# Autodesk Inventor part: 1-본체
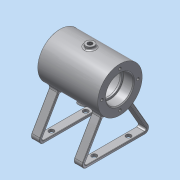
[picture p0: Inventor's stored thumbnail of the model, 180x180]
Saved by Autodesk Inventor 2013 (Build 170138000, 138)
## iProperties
Created: 2016-03
Part Number: 1-본체
Material: 알루미늄 6061
Document SubType Name: Modeling
Designer: Administrator
Mass: 213.146 g
Surface Area: 333.946 cm^2
Volume: 78.6517 cm^3
Density: 2.71 g/cm^3
Author: Administrator
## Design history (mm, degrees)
sketch "스케치1"
  geometry: C1 r 26 at (0, 0); 1 further point
  constraints: 1 centre point, 1 coincident
  dimensions: "d0" = 52 diameter of C1
extrude "돌출1" new body sketch "스케치1" stored distance "d2" = 70; taper "d3" = 0 deg
node "작업 평면1"
sketch "스케치2"
  geometry: C1 r 5 at (0, 0); 1 further point
  constraints: 1 centre point, 1 coincident
  dimensions: "d5" = 10 diameter of C1
extrude "돌출2" join sketch "스케치2" distance "d7" = 26; taper "d8" = 0 deg
sketch "스케치3"
  geometry: L1 (0, 0)-(0, -26); L2 (0, 0)-(7.506, -28.012); L3 (-1.968, -15.836)-(1.71, -29.565); L4 (1.71, -29.565)-(7.506, -28.012); L5 (7.506, -28.012)-(3.827, -14.283); L6 (3.827, -14.283)-(-1.968, -15.836); 1 further point
  constraints: 12 end point, 3 parallel, 1 collinear, 1 perpendicular, 1 vertical, 1 vertical alignment, 1 other
  dimensions: "d9" = 15 deg angle of L2 L1; "d10" = 12 diameter of L3 L2; "d12" = 29 distance from line of L4 point (0, 0)
revolve "회전1" sketch "스케치3" stored, may be unused: angle "d13" = 90 deg
node "작업 평면2"
sketch "스케치4"
  geometry: L1 (-16.613, -20)-(-38.264, -57.5); L2 (-33.934, -65)-(33.934, -65); L3 (38.264, -57.5)-(16.613, -20); L4 (0, 0)-(0, -65); L5 (-16.613, -20)-(16.613, -20); A1 r 5 centre (-33.934, -60) between (-38.264, -57.5) and (-33.934, -65); A2 r 5 centre (33.934, -60) between (33.934, -65) and (38.264, -57.5); A3 r 26 centre (0, 0) between (-16.613, -20) and (16.613, -20) reference
  constraints: 10 end point, 7 point on circle, 3 tangent, 2 centre point, 1 equal length, 1 equal radius, 1 horizontal, 1 midpoint, 1 perpendicular, 1 vertical alignment
  dimensions: "d16" = 5 radius of A1; "d20" = 45 distance between parallel lines of L2 L5; "d21" = 65 distance from line of L4.start L2; "d23" = 30 deg angle of L4 L1; "d24" = 30 deg angle of L3 L4
extrude "돌출3" new body sketch "스케치4" distance "d25" = 10; taper "d26" = 0 deg
sketch "스케치5"
  geometry: L1 (-16.613, -20)-(-38.264, -57.5) reference; L2 (38.264, -57.5)-(16.613, -20) reference; L3 (-33.934, -65)-(33.934, -65) reference; L4 (-14.183, -21.791)-(-35.666, -59); L5 (-33.934, -62)-(33.934, -62); L6 (35.666, -59)-(14.183, -21.791); A1 r 5 centre (-33.934, -60) between (-38.264, -57.5) and (-33.934, -65) reference; A2 r 26 centre (0, 0) between (-16.613, -20) and (16.613, -20) reference; A3 r 5 centre (33.934, -60) between (33.934, -65) and (38.264, -57.5) reference; A4 r 2 centre (-33.934, -60) between (-35.666, -59) and (-33.934, -62); A5 r 2 centre (33.934, -60) between (33.934, -62) and (35.666, -59); A6 r 26 centre (0, 0) between (-14.183, -21.791) and (14.183, -21.791); 1 further point
  constraints: 8 end point, 8 point on circle, 3 centre point, 1 coincident, 1 concentric, 2 other
  dimensions: "d27" = 3 distance between parallel lines of L1 L4; "d28" = 3 distance between parallel lines of L2 L6; "d29" = 3 distance between parallel lines of L3 L5
  node "투영된 루프2"
feature "결합1"
  node "솔리드2"
extrude "돌출4" cut sketch "스케치5" distance "d30" = 10; taper "d31" = 0 deg
node "작업 평면4"
sketch "스케치7"
  geometry: L1 (-6.533, -4.268)-(-6.533, 4.268); L2 (-6.533, 4.268)-(6.533, 4.268); L3 (6.533, 4.268)-(6.533, -4.268); L4 (6.533, -4.268)-(-6.533, -4.268); L5 (-26, -35)-(26, -35) reference; L6 (-26, -35)-(-26, 35) reference; 4 further points
  constraints: 2 midpoint, 1 horizontal alignment, 1 vertical alignment, 2 other
  dimensions: "d38" = 26 distance from line of L6 point (0, 0); "d39" = 35 distance from line of point (0, 0) L5; "d40" = 13.0662 distance between parallel lines of L1 L3; "d41" = 8.53659 distance between parallel lines of L2 L4; "d42" = 6.5331 distance from line of point (0, 0) L3
feature "엠보싱2" sketch "스케치7" dims "d16" = 5, "d20" = 45, "d21" = 65, "d23" = 30 deg, "d24" = 30 deg, "d43" = 0.5, "d44" = 0
hole "구멍1" diameter "d47" = 28; stored, may be unused: countersink angle "d51" = 90 deg, drill point angle "d53" = 0 deg; dims "d45" = 10, "d46" = 10, "d48" = 6, "d49" = 32, "d50" = 12, "d52" = 8
hole "구멍2" diameter "d56" = 32; stored, may be unused: countersink angle "d60" = 90 deg, drill point angle "d62" = 0 deg; dims "d54" = 10, "d55" = 10, "d57" = 6, "d58" = 32, "d59" = 12, "d61" = 12
sketch "스케치8"
  geometry: L1 (-16, 35)-(16, 35) reference; L2 (16, -35)-(-16, -35) reference; L3 (0, 35)-(0, -35); L4 (18, 21)-(0, 21); L5 (0, 21)-(0, -21); L6 (0, -21)-(18, -21); L7 (21, -18)-(21, 18); A1 r 3 centre (18, 18) between (21, 18) and (18, 21); A2 r 3 centre (18, -18) between (18, -21) and (21, -18); 4 further points
  constraints: 10 end point, 4 midpoint, 4 point on circle, 4 tangent, 2 centre point, 2 coincident, 2 parallel, 1 equal radius, 1 horizontal, 1 perpendicular, 1 vertical alignment
  dimensions: "d68" = 42 diameter of L7 L3; "d70" = 42 distance between parallel lines of L4 L6; "d71" = 3 radius of A1
revolve "회전2" sketch "스케치8" stored, may be unused: angle "d72" = 90 deg
sketch "스케치9"
  geometry: 2 further points
  constraints: 1 vertical alignment
  dimensions: "d73" = 21 distance of point (0, 0) point (0, 21)
hole "구멍3" sketch "스케치9" at (0, 21) diameter "d74" = 3.242; stored, may be unused: countersink angle "d78" = 90 deg, drill point angle "d80" = 118 deg; dims "d75" = 8, "d76" = 32, "d77" = 12, "d79" = 10
sketch "스케치10"
  geometry: L1 (-5, 0)-(-5, -10) reference; L2 (-5, -50)-(-5, -60) reference; 7 further points
  constraints: 4 horizontal alignment, 2 midpoint, 2 vertical alignment
  dimensions: "d84" = 20 horizontal distance of point (33.934, -30) point (13.934, -5); "d85" = 40 distance of point (53.934, -5) point (13.934, -5)
hole "구멍4" sketch "스케치10" at (13.934, -5), (53.934, -5), (13.934, -55), (53.934, -55) diameter "d86" = 6; stored, may be unused: countersink angle "d90" = 90 deg, drill point angle "d92" = 118 deg; dims "d87" = 6, "d88" = 32, "d89" = 12, "d91" = 10
hole "구멍5" diameter "d95" = 5.188; stored, may be unused: countersink angle "d99" = 90 deg, drill point angle "d101" = 0 deg; dims "d96" = 19, "d97" = 32, "d98" = 12, "d100" = 20, "d104" = 10, "d105" = 10
hole "구멍6" diameter "d106" = 5.188; stored, may be unused: countersink angle "d110" = 90 deg, drill point angle "d112" = 0 deg; dims "d102" = 10, "d103" = 10, "d107" = 14, "d108" = 32, "d109" = 12, "d111" = 15
fillet "모깎기1" dims "d113" = 2
chamfer "모따기1" distance "d114" = 1; stored, may be unused: second distance "d115" = 2, angle "d116" = 45 deg
fillet "모깎기2" dims "d117" = 0.3
fillet "모깎기3" dims "d118" = 0.5
fillet "모깎기4" dims "d119" = 0.5
fillet "모깎기5" dims "d120" = 3
node "솔리드1"
mirror "대칭1"
mirror "대칭2"
pattern_circular "원형 패턴1" dims angle "d82" = 360 deg
mirror "대칭3"
node "투영된 루프1"
other parameters: "d4" = 29
